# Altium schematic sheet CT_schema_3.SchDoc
size 283 x 147 mm
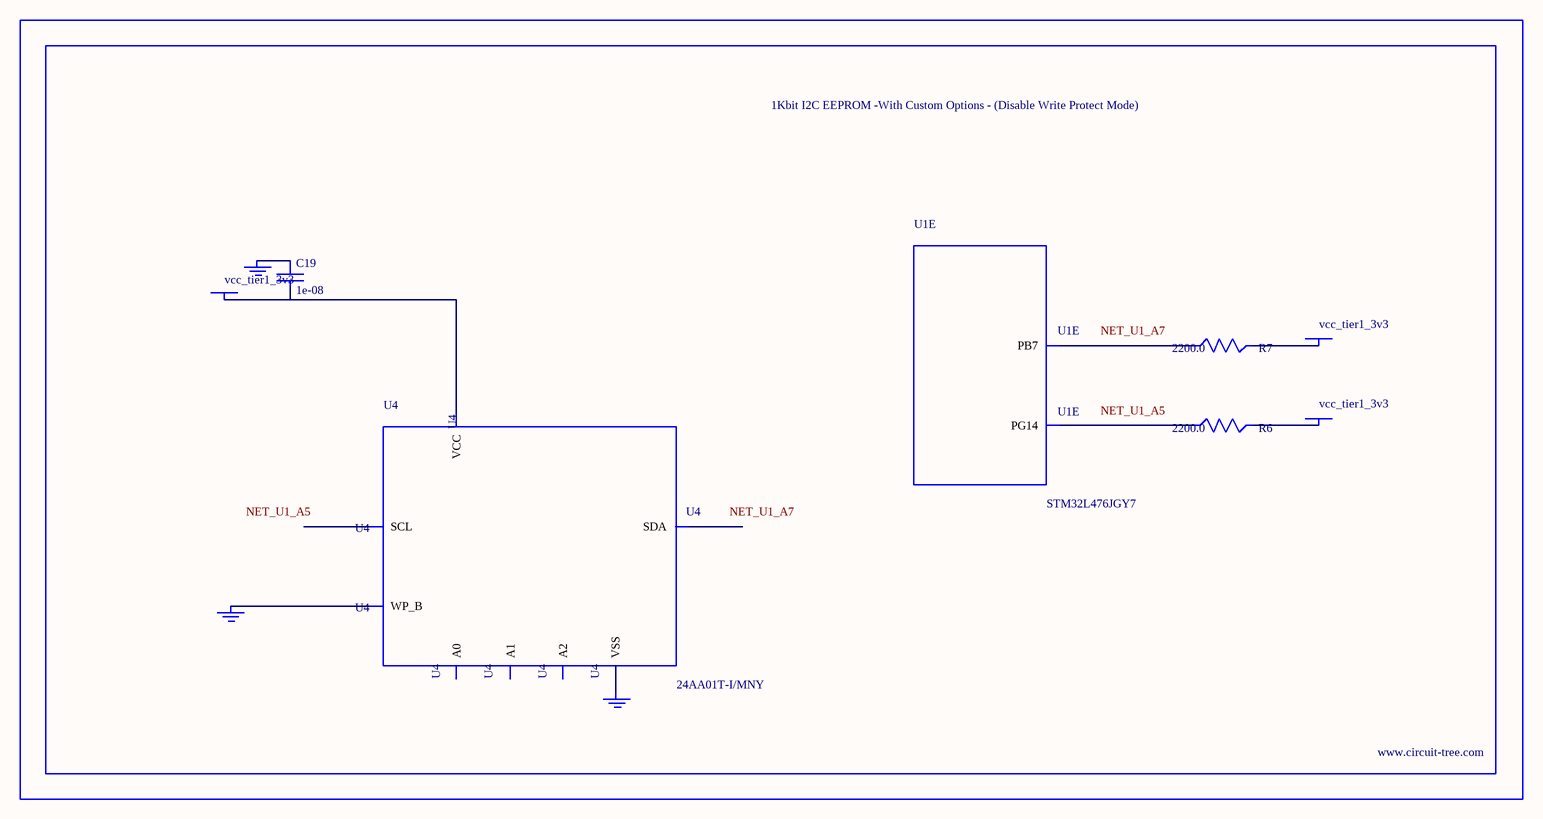
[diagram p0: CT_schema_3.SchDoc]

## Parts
BORDER2  (no value)
C19  1e-08  [C0402]
GND_INSTANCE_2_0  (no value)
GND_INSTANCE_2_1  (no value)
GND_INSTANCE_2_2  (no value)
POWER_INSTANCE_2_0  vcc_tier1_3v3
POWER_INSTANCE_2_1  vcc_tier1_3v3
POWER_INSTANCE_2_2  vcc_tier1_3v3
R6  2200.0  [R0603]
R7  2200.0  [R0603]
U1  STM32L476JGY7  [WLCSP72]  (part E of 8)
U4  24AA01T-I/MNY  [TDFN-8/6MM]

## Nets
NetC19_1: C19.1 GND_INSTANCE_2_1.0(GND)
NetC19_2: C19.2 POWER_INSTANCE_2_0.0(PWR) U4.8(VCC)
NetGND_INSTANCE_2_0_0: GND_INSTANCE_2_0.0(GND) U4.7(WP_B)
NetGND_INSTANCE_2_2_0: GND_INSTANCE_2_2.0(GND) U4.4(VSS)
NetPOWER_INSTANCE_2_1_0: POWER_INSTANCE_2_1.0(PWR) R7.2
NetPOWER_INSTANCE_2_2_0: POWER_INSTANCE_2_2.0(PWR) R6.2
NetR6_1: R6.1 U1.A5(PG14)
NetR7_1: R7.1 U1.A7(PB7)

Not connected (* = marked no-connect by the designer): U4 1(A0) 2(A1) 3(A2) 5(SDA) 6(SCL)

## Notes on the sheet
- Labels drawn without touching a wire or pin: NET_U1_A5, NET_U1_A7

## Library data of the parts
BORDER2 = BORDER_PAGE2
C19 = C0402C103K3RAC
GND_INSTANCE_2_0-GND_INSTANCE_2_2 = GND
POWER_INSTANCE_2_0-POWER_INSTANCE_2_2 = PWR
R6 R7 = RC0603JR-072K2L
